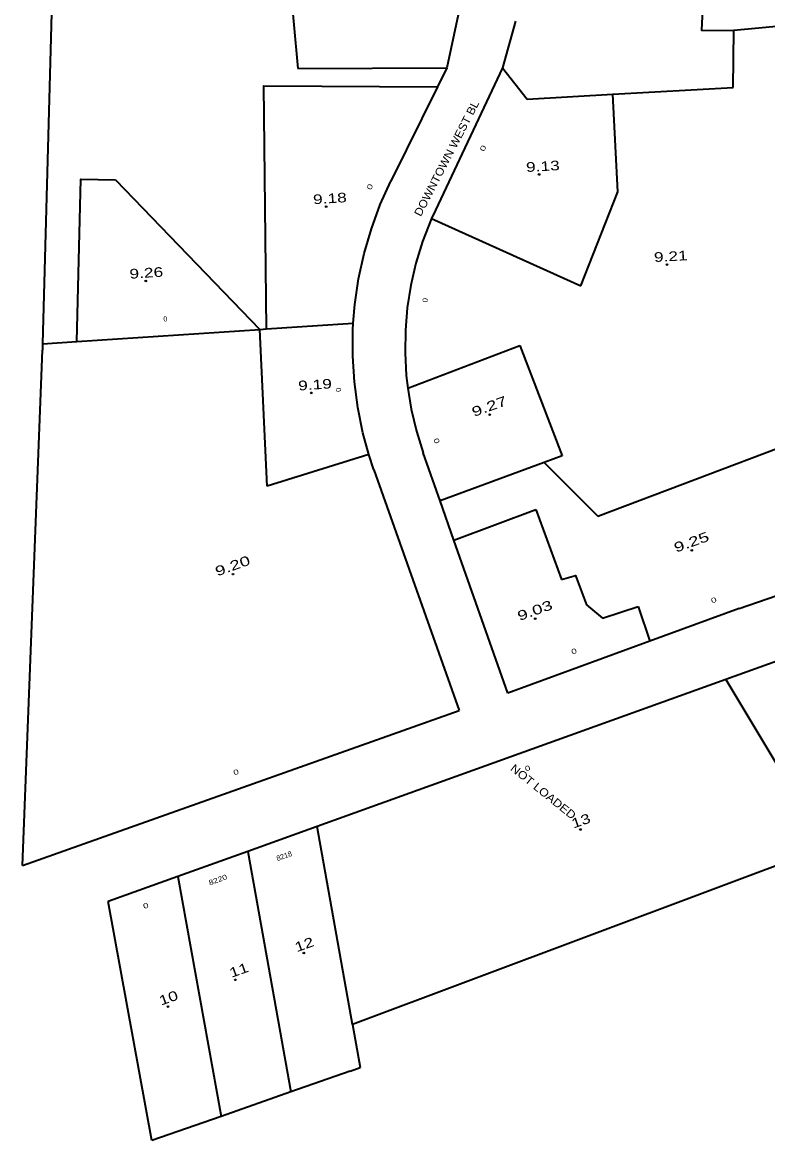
# Model space of a CAD drawing. Extents: x 2544898 to 2547598, y 582139 to 585083.
# Drawn here: x 2544898 to 2546061, y 582139 to 583885 of the extents above; entities that cross this region are included whole.
import ezdxf
from ezdxf.enums import TextEntityAlignment as Align

# ---------------------------------------------------------------- set-up
doc = ezdxf.new("R2010")
doc.units = 0
doc.header["$LTSCALE"] = 5
doc.header["$PDMODE"] = 32
doc.header["$PDSIZE"] = 2.5
for name, color, linetype in [('20', 7, 'Continuous'), ('38', 7, 'Continuous'), ('39', 7, 'Continuous'), ('41', 7, 'Continuous')]:
    doc.layers.add(name, color=color, linetype=linetype)
doc.layers.add('40', color=7, linetype='Continuous', lineweight=35)

msp = doc.modelspace()

# ---------------------------------------------------------------- linework, layer by layer
at = {"layer": '40'}
for p, q in [((2545598.034, 583991.551), (2545560.252, 583813.923)), ((2545667.328, 583886.973), (2545647.379, 583814.255)), ((2546119.727, 583883.075), (2546008.192, 583872.182)), ((2546007.307, 583783.509), (2546008.192, 583872.182)), ((2545327.98, 583813.17), (2545560.252, 583813.923)), ((2545647.379, 583814.255), (2545542.674, 583591.93)), ((2545560.252, 583813.923), (2545545.59, 583784.189)), ((2545647.379, 583814.255), (2545685.956, 583765.249)), ((2545545.59, 583784.189), (2545473.166, 583637.309)), ((2545685.956, 583765.249), (2545819.349, 583772.829)), ((2545043.059, 583638.943), (2545268.649, 583405.733)), ((2545769.398, 583473.633), (2545827.214, 583620.518)), ((2545279.153, 583406.426), (2545414.403, 583415.351)), ((2544982.704, 583386.864), (2545268.649, 583405.733)), ((2545268.649, 583405.733), (2545279.153, 583406.426)), ((2545268.649, 583405.733), (2545268.649, 583405.732)), ((2545279.777, 583160.747), (2545268.649, 583405.732)), ((2544929.396, 583383.346), (2544929.123, 583373.341)), ((2545674.256, 583380.478), (2545740.143, 583208.187)), ((2544897.936, 582568.667), (2544929.123, 583373.341)), ((2545796.27, 583114.276), (2546098.826, 583228.71)), ((2545438.835, 583210.106), (2545279.777, 583160.747)), ((2545446.649, 583186.245), (2545438.835, 583210.106)), ((2545549.746, 583138.053), (2545523.428, 583212.756)), ((2545740.143, 583208.187), (2545712.467, 583197.993)), ((2545446.649, 583186.245), (2545579.88, 582810.403)), ((2545712.467, 583197.993), (2545549.746, 583138.053)), ((2545712.467, 583197.993), (2545796.27, 583114.276)), ((2545571.387, 583076.624), (2545549.746, 583138.053)), ((2545699.099, 583124.223), (2545739.103, 583015.014)), ((2546016.803, 582969.9), (2546090.403, 582995.582)), ((2545778.146, 582975.859), (2545803.251, 582954.836)), ((2545803.251, 582954.836), (2545859.252, 582973.182)), ((2545859.252, 582973.182), (2545877.385, 582918.793)), ((2546016.803, 582969.9), (2545877.385, 582918.793)), ((2545877.385, 582918.793), (2545655.629, 582837.504)), ((2545995.927, 582859.287), (2545357.938, 582629.661)), ((2544897.936, 582568.667), (2545579.88, 582810.403)), ((2545357.938, 582629.661), (2545249.557, 582590.652)), ((2545413.122, 582320.217), (2545357.938, 582629.661)), ((2545249.557, 582590.652), (2545317.093, 582215.217)), ((2545140.708, 582551.475), (2545031.998, 582512.348)), ((2545099.922, 582139.068), (2545031.998, 582512.348)), ((2545409.515, 582247.623), (2545317.093, 582215.217)), ((2545409.515, 582247.623), (2545425.191, 582253.127)), ((2545317.093, 582215.217), (2545208.073, 582176.99)), ((2545208.073, 582176.99), (2545099.922, 582139.068))]:
    msp.add_line(p, q, dxfattribs=at)
for points in [[(2544959.672, 584492.287), (2544929.396, 583383.346), (2544982.704, 583386.864)], [(2545576.597, 584134.867), (2545300.592, 584109.014), (2545327.98, 583813.17)], [(2545967.366, 584062.573), (2545957.585, 583873.033), (2546008.192, 583872.182)], [(2545279.153, 583406.426), (2545274.525, 583785.894), (2545545.59, 583784.189)], [(2545827.214, 583620.518), (2545819.349, 583772.829), (2546007.307, 583783.509)], [(2544982.704, 583386.864), (2544989.056, 583640.227), (2545043.059, 583638.943)], [(2545414.403, 583415.351), (2545416.825, 583444.614), (2545422.676, 583484.535), (2545431.284, 583523.953), (2545442.607, 583562.678), (2545456.59, 583600.525), (2545473.166, 583637.309)], [(2545542.674, 583591.93), (2545536.714, 583578.672), (2545769.398, 583473.633)], [(2545536.714, 583578.672), (2545522.639, 583542.777), (2545512.228, 583508.947), (2545504.238, 583474.466), (2545498.706, 583439.506), (2545495.662, 583404.241), (2545495.12, 583368.85), (2545497.083, 583333.509), (2545499.327, 583313.663), (2545674.256, 583380.478)], [(2545438.835, 583210.106), (2545429.431, 583244.249), (2545421.346, 583283.777), (2545416.024, 583323.771), (2545413.491, 583364.039), (2545413.758, 583404.384), (2545414.403, 583415.351)], [(2545499.327, 583313.663), (2545504.7, 583280.979), (2545512.856, 583246.536), (2545523.428, 583212.756)], [(2545655.629, 582837.504), (2545571.387, 583076.624), (2545699.099, 583124.223)], [(2545739.103, 583015.014), (2545761.3, 583021.578), (2545778.146, 582975.859)], [(2546376.823, 582996.041), (2545995.927, 582859.287), (2546152.65, 582597.539)], [(2545249.557, 582590.652), (2545140.708, 582551.475), (2545208.073, 582176.99)], [(2546151.992, 582597.298), (2545413.122, 582320.217), (2545425.191, 582253.127)]]:
    msp.add_lwpolyline(points, dxfattribs=at)
at = {"layer": '41'}
for p in [(2545704.428, 583647.551), (2545372.016, 583597.3), (2545904.007, 583506.886), (2545090.52, 583481.301), (2545348.765, 583306.553), (2545627.178, 583272.471), (2545942.672, 583060.64), (2545226.6, 583023.472), (2545698.342, 582953.891), (2545768.923, 582624.894), (2545337.18, 582431.895), (2545230.431, 582390.145), (2545125.266, 582348.395)]:
    msp.add_point(p, dxfattribs=at)

# ---------------------------------------------------------------- texts
at = {"layer": '20'}
for s, rotation, width, p in [('DOWNTOWN WEST BL', 62.77, 1.1, (2545565.573, 583669.918)), ('NOT LOADED', 321.152, 1.15, (2545706.966, 582678.99))]:
    msp.add_text(s, height=12.5, rotation=rotation, dxfattribs=dict(at, width=width)).set_placement(p, align=Align.CENTER)
at = {"layer": '38'}
for s, rotation, width, p in [('9.13', 3.252, 1.35, (2545710.697, 583652.883)), ('9.18', 3.775, 1.35, (2545378.355, 583602.711)), ('9.21', 3.252, 1.35, (2545910.32, 583512.298)), ('9.26', 3.775, 1.35, (2545091.862, 583486.438)), ('9.19', 3.775, 1.35, (2545355.101, 583311.94)), ('9.27', 19.75, 1.45, (2545629.148, 583278.465)), ('9.25', 19.75, 1.45, (2545944.662, 583066.628)), ('9.20', 19.75, 1.45, (2545228.566, 583029.506)), ('9.03', 19.75, 1.45, (2545700.292, 582959.855)), ('13', 19.75, 1.35, (2545772.127, 582631.337)), ('12', 19.75, 1.35, (2545340.346, 582438.27)), ('11', 19.75, 1.35, (2545238.296, 582398.24)), ('10', 19.75, 1.35, (2545128.456, 582354.858))]:
    msp.add_text(s, height=15, rotation=rotation, dxfattribs=dict(at, width=width)).set_placement(p, align=Align.CENTER)
at = {"layer": '39'}
for s, rotation, width, p in [('0', 64.782, 1.55, (2545620.51, 583686.772)), ('0', 66.738, 1.5, (2545443.912, 583626.718)), ('0', 82.022, 1.15, (2545530.581, 583450.613)), ('0', 276.583, 1.1, (2545387.264, 583310.923)), ('0', 288.392, 1.4, (2545540.713, 583230.384)), ('0', 20.131, 1.45, (2545978.354, 582979.207)), ('0', 20.131, 1.45, (2545760.278, 582899.314)), ('0', 19.518, 1.4, (2545232.792, 582710.683)), ('0', 19.795, 1.4, (2545687.754, 582716.57)), ('8218', 19.795, 1.05, (2545307.854, 582579.76)), ('8220', 19.795, 1.25, (2545204.401, 582542.597)), ('0', 19.795, 1.4, (2545091.923, 582502.065))]:
    msp.add_text(s, height=8, rotation=rotation, dxfattribs=dict(at, width=width)).set_placement(p, align=Align.CENTER)
msp.add_text('0', height=8, rotation=3.775, dxfattribs=at).set_placement((2545121.316, 583418.051), align=Align.CENTER)

doc.saveas('drawing.dxf')
